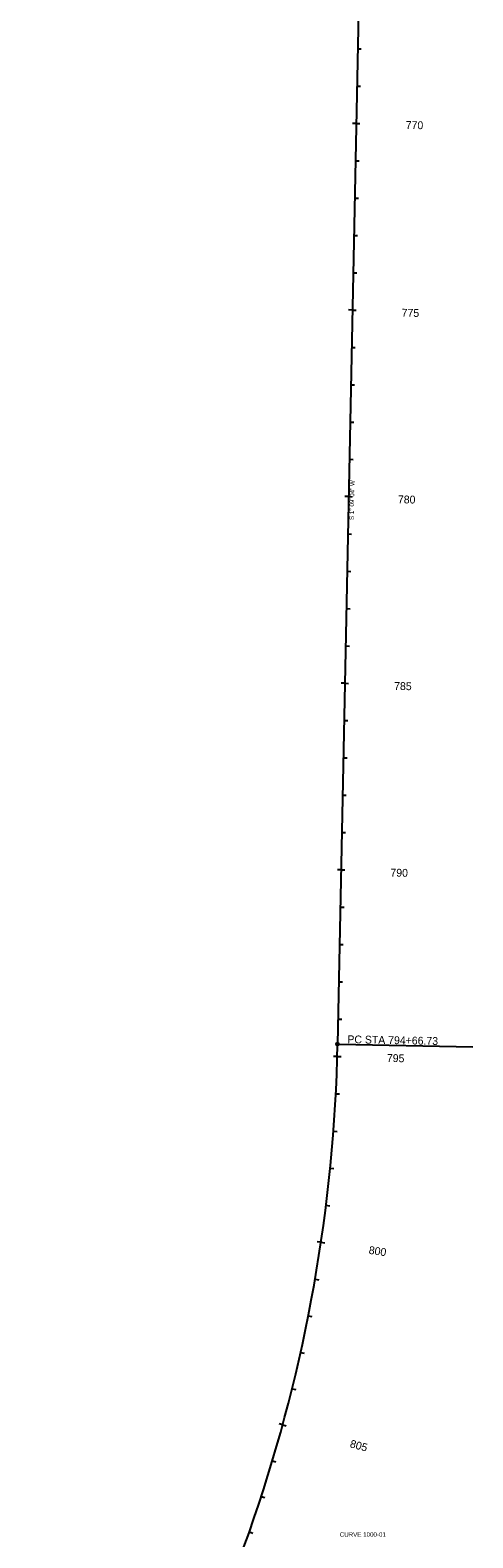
# Model space of a CAD drawing. Extents: x 2819977 to 2827606, y 113942 to 150283.
# Drawn here: x 2822878 to 2824063, y 138086 to 142125 of the extents above; entities that cross this region are included whole.
import ezdxf

# ---------------------------------------------------------------- set-up
doc = ezdxf.new("R2010")
doc.units = 0
for name, color, linetype in [('Level 63', 7, 'Continuous'), ('Roadway-Safety', 7, 'Continuous'), ('Roadway-Signs', 7, 'Continuous'), ('Roadway-Walls', 7, 'Continuous'), ('Utility-Power', 7, 'Continuous')]:
    doc.layers.add(name, color=color, linetype=linetype)

msp = doc.modelspace()

# ---------------------------------------------------------------- linework, layer by layer
at = {"layer": 'Level 63'}
msp.add_circle((2823701.1, 139408.5), 4, dxfattribs=at)
at = {"layer": 'Roadway-Safety'}
msp.add_line((2823705.1, 139408.5), (2824063, 139401.3), dxfattribs=at)
at = {"layer": 'Utility-Power'}
for p, q in [((2823760.8, 142380.9), (2823701.1, 139408.5)), ((2823754.6, 142074.7), (2823764.6, 142074.5)), ((2823752.6, 141974.8), (2823762.6, 141974.6)), ((2823750.6, 141874.8), (2823740.6, 141875)), ((2823750.6, 141874.8), (2823760.6, 141874.6)), ((2823748.6, 141774.8), (2823758.6, 141774.6)), ((2823746.6, 141674.8), (2823756.6, 141674.6)), ((2823744.6, 141574.8), (2823754.6, 141574.6)), ((2823742.6, 141474.9), (2823752.6, 141474.7)), ((2823740.6, 141374.9), (2823730.6, 141375.1)), ((2823740.6, 141374.9), (2823750.6, 141374.7)), ((2823738.6, 141274.9), (2823748.5, 141274.7)), ((2823736.5, 141174.9), (2823746.5, 141174.7)), ((2823734.5, 141074.9), (2823744.5, 141074.7)), ((2823732.5, 140975), (2823742.5, 140974.8)), ((2823730.5, 140875), (2823720.5, 140875.2)), ((2823730.5, 140875), (2823740.5, 140874.8)), ((2823728.5, 140775), (2823738.5, 140774.8)), ((2823726.5, 140675), (2823736.5, 140674.8)), ((2823724.5, 140575), (2823734.5, 140574.8)), ((2823722.5, 140475.1), (2823732.5, 140474.9)), ((2823720.5, 140375.1), (2823710.5, 140375.3)), ((2823720.5, 140375.1), (2823730.5, 140374.9)), ((2823718.5, 140275.1), (2823728.5, 140274.9)), ((2823716.5, 140175.1), (2823726.5, 140174.9)), ((2823714.4, 140075.1), (2823724.4, 140074.9)), ((2823712.4, 139975.2), (2823722.4, 139975)), ((2823710.4, 139875.2), (2823700.4, 139875.4)), ((2823710.4, 139875.2), (2823720.4, 139875)), ((2823708.4, 139775.2), (2823718.4, 139775)), ((2823706.4, 139675.2), (2823716.4, 139675)), ((2823704.4, 139575.2), (2823714.4, 139575)), ((2823702.4, 139475.3), (2823712.4, 139475.1)), ((2823700.3, 139375.3), (2823690.3, 139375.6)), ((2823700.3, 139375.3), (2823710.2, 139375)), ((2823696.3, 139275.4), (2823706.2, 139274.9)), ((2823689.9, 139175.6), (2823699.9, 139174.8)), ((2823681.2, 139076), (2823691.1, 139075)), ((2823670, 138976.6), (2823680, 138975.4)), ((2823656.6, 138877.5), (2823646.7, 138879)), ((2823656.6, 138877.5), (2823666.5, 138876)), ((2823640.7, 138778.8), (2823650.6, 138777.1)), ((2823622.6, 138680.4), (2823632.4, 138678.5)), ((2823602.1, 138582.6), (2823611.8, 138580.4)), ((2823579.2, 138485.2), (2823588.9, 138482.8)), ((2823554.1, 138388.4), (2823544.4, 138391)), ((2823554.1, 138388.4), (2823563.7, 138385.8)), ((2823526.6, 138292.3), (2823536.2, 138289.4)), ((2823496.9, 138196.8), (2823506.4, 138193.7)), ((2823464.9, 138102), (2823474.3, 138098.7))]:
    msp.add_line(p, q, dxfattribs=at)
msp.add_arc((2819501.9, 139492.9), 4200, 323.5041, 358.849, dxfattribs=at)

# ---------------------------------------------------------------- texts
at = {"layer": 'Roadway-Safety'}
msp.add_text('PC STA 794+66.73', height=21, rotation=358.849, dxfattribs=at).set_placement((2823727.1, 139411))
at = {"layer": 'Roadway-Signs'}
msp.add_text('S 1%%d 09\' 04" W', height=12, rotation=88.849, dxfattribs=at).set_placement((2823744.3, 140812.2))
at = {"layer": 'Roadway-Walls'}
msp.add_text('CURVE 1000-01', height=12, dxfattribs=at).set_placement((2823706.9, 138088.8))
at = {"layer": 'Utility-Power'}
for s, rotation, p in [(' 770', 358.849, (2823875.5, 141860.3)), (' 775', 358.849, (2823864.6, 141357.4)), (' 780', 358.849, (2823854.6, 140857.5)), (' 785', 358.849, (2823844.5, 140357.6)), (' 790', 358.849, (2823834.5, 139857.7)), (' 795', 358.3951, (2823825, 139361.2)), (' 800', 351.5742, (2823775.7, 138848.1)), (' 805', 344.7533, (2823725, 138331))]:
    msp.add_text(s, height=21, rotation=rotation, dxfattribs=at).set_placement(p)

doc.saveas('drawing.dxf')
